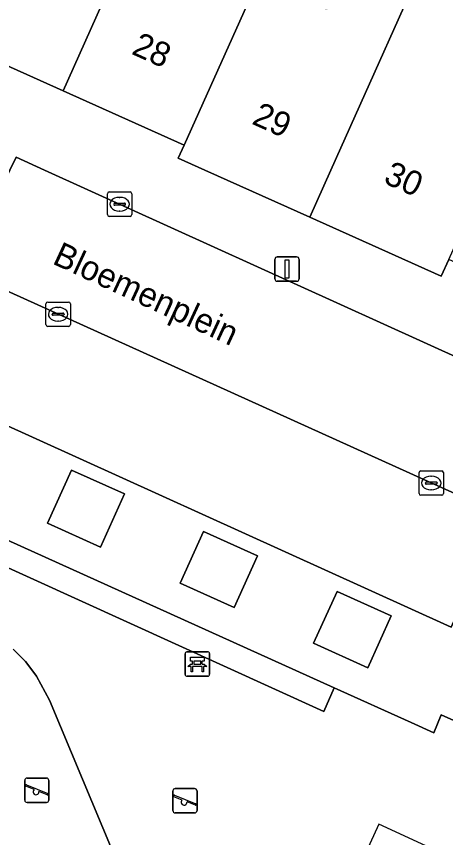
# Model space of a CAD drawing. Extents: x 161838 to 162344, y 381620 to 382160.
# Drawn here: x 162191.19 to 162208.76, y 381722.64 to 381756.3 of the extents above; entities that cross this region are included whole.
import ezdxf

# ---------------------------------------------------------------- set-up
doc = ezdxf.new("R2010")
doc.units = 0
for name, color, linetype in [('IMGEO_Bank', 7, 'Continuous'), ('IMGEO_Groenvoorziening', 7, 'Continuous'), ('IMGEO_Haag', 7, 'Continuous'), ('IMGEO_Hek', 7, 'Continuous'), ('IMGEO_Kolk', 7, 'Continuous'), ('IMGEO_Lichtmast', 7, 'Continuous'), ('IMGEO_Openbare_ruimte_label', 7, 'Continuous'), ('IMGEO_Pand', 7, 'Continuous'), ('IMGEO_Pand_nummerreeks', 7, 'Continuous'), ('IMGEO_Parkeervlak_open', 7, 'Continuous'), ('IMGEO_Rijbaan_lokaal_open', 7, 'Continuous'), ('IMGEO_Speelvoorziening', 7, 'Continuous'), ('IMGEO_Terreindeel_zand', 7, 'Continuous'), ('IMGEO_Voetpad_open', 7, 'Continuous')]:
    doc.layers.add(name, color=color, linetype=linetype)

msp = doc.modelspace()

# ---------------------------------------------------------------- linework, layer by layer
at = {"layer": 'IMGEO_Bank'}
for p, q in [((162198.099, 381729.327), (162198.099, 381730.168)), ((162198.099, 381730.168), (162198.099, 381729.327)), ((162198.174, 381730.252), (162199.015, 381730.252)), ((162199.015, 381730.252), (162198.174, 381730.252)), ((162199.099, 381730.177), (162199.099, 381729.336)), ((162199.099, 381729.336), (162199.099, 381730.177)), ((162198.408, 381729.758), (162198.408, 381729.864)), ((162198.452, 381729.864), (162198.452, 381729.758)), ((162198.74, 381729.87), (162198.458, 381729.87)), ((162198.746, 381729.758), (162198.746, 381729.864)), ((162198.79, 381729.864), (162198.79, 381729.758)), ((162198.796, 381729.65), (162198.403, 381729.65)), ((162198.458, 381729.752), (162198.74, 381729.752)), ((162199.024, 381729.252), (162198.183, 381729.252)), ((162198.183, 381729.252), (162199.024, 381729.252))]:
    msp.add_line(p, q, dxfattribs=at)
for points in [[(162198.402, 381729.87), (162198.316, 381729.87), (162198.316, 381730.031), (162198.879, 381730.031), (162198.879, 381729.87), (162198.796, 381729.87)], [(162198.346, 381729.65), (162198.204, 381729.65), (162198.316, 381729.752), (162198.402, 381729.752)], [(162198.396, 381729.643), (162198.396, 381729.436), (162198.353, 381729.436), (162198.353, 381729.643)], [(162198.796, 381729.752), (162198.879, 381729.752), (162198.991, 381729.65), (162198.852, 381729.65)], [(162198.846, 381729.643), (162198.846, 381729.436), (162198.802, 381729.436), (162198.802, 381729.643)]]:
    msp.add_lwpolyline(points, dxfattribs=at)
for centre, radius, start, end in [((162198.177, 381730.174), 0.0779, 92.4484, 184.2845), ((162198.177, 381730.174), 0.0779, 92.4484, 184.2845), ((162199.021, 381730.174), 0.0779, 2.4484, 94.2845), ((162199.021, 381730.174), 0.0779, 2.4484, 94.2845), ((162198.401, 381729.863), 0.00671, 2.8957, 87.1043), ((162198.458, 381729.863), 0.00671, 92.8957, 177.1043), ((162198.74, 381729.863), 0.00671, 2.8957, 87.1043), ((162198.797, 381729.863), 0.00671, 92.8957, 177.1043), ((162198.346, 381729.643), 0.00671, 2.8957, 87.1043), ((162198.403, 381729.643), 0.00671, 92.8957, 177.1043), ((162198.401, 381729.759), 0.00671, 272.8957, 357.1043), ((162198.458, 381729.759), 0.00671, 182.8957, 267.1043), ((162198.74, 381729.759), 0.00671, 272.8957, 357.1043), ((162198.797, 381729.759), 0.00671, 182.8957, 267.1043), ((162198.795, 381729.643), 0.00671, 2.8957, 87.1043), ((162198.852, 381729.643), 0.00671, 92.8957, 177.1043), ((162198.177, 381729.33), 0.0779, 182.4484, 274.2845), ((162198.177, 381729.33), 0.0779, 182.4484, 274.2845), ((162199.021, 381729.33), 0.0779, 272.4484, 4.2845), ((162199.021, 381729.33), 0.0779, 272.4484, 4.2845)]:
    msp.add_arc(centre, radius, start, end, dxfattribs=at)
at = {"layer": 'IMGEO_Groenvoorziening'}
for points in [[(162224.972, 381729.54), (162213.092, 381734.851), (162212.642, 381733.768), (162211.534, 381734.306), (162210.084, 381730.982), (162212.783, 381729.769), (162211.371, 381726.432), (162208.583, 381727.67), (162208.284, 381726.931), (162207.356, 381727.351), (162204.208, 381728.775), (162203.782, 381727.8), (162185.802, 381735.987), (162186.225, 381736.908), (162183.113, 381738.321), (162181.971, 381738.914), (162180.968, 381740.762), (162179.108, 381743.016)], [(162191.06, 381730.357), (162191.564, 381729.849), (162191.947, 381729.349), (162192.014, 381729.249), (162192.541, 381728.271), (162195.625, 381720.87)]]:
    msp.add_lwpolyline(points, dxfattribs=at)
for points in [[(162194.629, 381734.546), (162195.615, 381736.725), (162193.453, 381737.702), (162192.467, 381735.523)], [(162186.225, 381736.908), (162185.802, 381735.987), (162203.782, 381727.8), (162204.208, 381728.775)], [(162200.11, 381732.065), (162201.069, 381734.186), (162198.858, 381735.186), (162197.899, 381733.065)], [(162205.581, 381729.598), (162206.542, 381731.724), (162204.325, 381732.727), (162203.363, 381730.601)]]:
    msp.add_lwpolyline(points, close=True, dxfattribs=at)
at = {"layer": 'IMGEO_Haag'}
msp.add_lwpolyline([(162186.225, 381736.908), (162185.802, 381735.987), (162203.782, 381727.8), (162204.208, 381728.775)], close=True, dxfattribs=at)
at = {"layer": 'IMGEO_Hek'}
for points in [[(162206.028, 381723.192), (162200.769, 381711.668), (162200.712, 381710.292), (162201.108, 381709.061), (162201.974, 381708.184), (162206.767, 381705.976)], [(162212.925, 381719.997), (162206.028, 381723.192)]]:
    msp.add_lwpolyline(points, dxfattribs=at)
at = {"layer": 'IMGEO_Kolk'}
for p, q in [((162194.917, 381748.179), (162194.917, 381749.031)), ((162194.992, 381749.105), (162195.844, 381749.105)), ((162195.918, 381749.031), (162195.918, 381748.179)), ((162195.405, 381748.885), (162195.43, 381748.885)), ((162195.176, 381748.599), (162195.176, 381748.611)), ((162195.614, 381748.562), (162195.216, 381748.562)), ((162195.219, 381748.648), (162195.617, 381748.648)), ((162195.66, 381748.611), (162195.66, 381748.599)), ((162195.844, 381748.105), (162194.992, 381748.105)), ((162195.428, 381748.325), (162195.403, 381748.325)), ((162192.399, 381743.667), (162192.399, 381744.519)), ((162192.474, 381744.593), (162193.326, 381744.593)), ((162192.887, 381744.373), (162192.912, 381744.373)), ((162193.4, 381744.519), (162193.4, 381743.667)), ((162192.658, 381744.087), (162192.658, 381744.099)), ((162193.096, 381744.05), (162192.698, 381744.05)), ((162192.701, 381744.136), (162193.099, 381744.136)), ((162193.142, 381744.099), (162193.142, 381744.087)), ((162192.91, 381743.813), (162192.885, 381743.813)), ((162193.326, 381743.593), (162192.474, 381743.593)), ((162207.678, 381736.746), (162207.678, 381737.598)), ((162207.753, 381737.672), (162208.605, 381737.672)), ((162208.679, 381737.598), (162208.679, 381736.746)), ((162208.166, 381737.452), (162208.191, 381737.452)), ((162207.937, 381737.166), (162207.937, 381737.178)), ((162208.375, 381737.129), (162207.977, 381737.129)), ((162207.98, 381737.215), (162208.378, 381737.215)), ((162208.189, 381736.892), (162208.164, 381736.892)), ((162208.421, 381737.178), (162208.421, 381737.166)), ((162208.605, 381736.672), (162207.753, 381736.672))]:
    msp.add_line(p, q, dxfattribs=at)
for points in [[(162194.917, 381748.179), (162194.917, 381749.031)], [(162194.992, 381749.105), (162195.844, 381749.105)], [(162195.918, 381749.031), (162195.918, 381748.179)], [(162195.844, 381748.105), (162194.992, 381748.105)], [(162192.399, 381743.667), (162192.399, 381744.519)], [(162192.474, 381744.593), (162193.326, 381744.593)], [(162193.4, 381744.519), (162193.4, 381743.667)], [(162193.326, 381743.593), (162192.474, 381743.593)], [(162207.678, 381736.746), (162207.678, 381737.598)], [(162207.753, 381737.672), (162208.605, 381737.672)], [(162208.679, 381737.598), (162208.679, 381736.746)], [(162208.605, 381736.672), (162207.753, 381736.672)]]:
    msp.add_lwpolyline(points, dxfattribs=at)
for centre, radius, start, end in [((162194.994, 381749.029), 0.0765, 91.552, 178.448), ((162194.994, 381749.029), 0.0765, 91.552, 178.448), ((162195.842, 381749.029), 0.0765, 1.552, 88.448), ((162195.842, 381749.029), 0.0765, 1.552, 88.448), ((162195.216, 381748.608), 0.0403, 85.8775, 175.7526), ((162195.213, 381748.598), 0.0366, 178.938, 274.7102), ((162195.617, 381748.605), 0.043, 264.8664, 352.4533), ((162195.621, 381748.61), 0.0386, 1.7309, 96.639), ((162194.994, 381748.181), 0.0765, 181.552, 268.448), ((162194.994, 381748.181), 0.0765, 181.552, 268.448), ((162195.842, 381748.181), 0.0765, 271.552, 358.448), ((162195.842, 381748.181), 0.0765, 271.552, 358.448), ((162192.476, 381744.517), 0.0765, 91.552, 178.448), ((162192.476, 381744.517), 0.0765, 91.552, 178.448), ((162193.324, 381744.517), 0.0765, 1.552, 88.448), ((162193.324, 381744.517), 0.0765, 1.552, 88.448), ((162192.698, 381744.096), 0.0403, 85.8775, 175.7526), ((162192.695, 381744.086), 0.0366, 178.938, 274.7102), ((162193.099, 381744.093), 0.043, 264.8664, 352.4533), ((162193.103, 381744.098), 0.0386, 1.7309, 96.639), ((162192.476, 381743.669), 0.0765, 181.552, 268.448), ((162192.476, 381743.669), 0.0765, 181.552, 268.448), ((162193.324, 381743.669), 0.0765, 271.552, 358.448), ((162193.324, 381743.669), 0.0765, 271.552, 358.448), ((162207.755, 381737.596), 0.0765, 91.552, 178.448), ((162207.755, 381737.596), 0.0765, 91.552, 178.448), ((162208.603, 381737.596), 0.0765, 1.552, 88.448), ((162208.603, 381737.596), 0.0765, 1.552, 88.448), ((162207.977, 381737.175), 0.0403, 85.8775, 175.7526), ((162207.974, 381737.165), 0.0366, 178.938, 274.7102), ((162208.378, 381737.172), 0.043, 264.8664, 352.4533), ((162208.382, 381737.177), 0.0386, 1.7309, 96.639), ((162207.755, 381736.748), 0.0765, 181.552, 268.448), ((162207.755, 381736.748), 0.0765, 181.552, 268.448), ((162208.603, 381736.748), 0.0765, 271.552, 358.448), ((162208.603, 381736.748), 0.0765, 271.552, 358.448)]:
    msp.add_arc(centre, radius, start, end, dxfattribs=at)
for centre, major_axis, ratio, start_param, end_param in [((162195.404, 381748.605), (-0.387, 0.002), 0.722429, 4.712389, 7.853982), ((162195.429, 381748.605), (-0.39, 0.002), 0.717154, 1.570796, 4.712389), ((162192.886, 381744.093), (-0.387, 0.002), 0.722429, 4.712389, 7.853982), ((162192.911, 381744.093), (-0.39, 0.002), 0.717154, 1.570796, 4.712389), ((162208.165, 381737.172), (-0.387, 0.002), 0.722429, 4.712389, 7.853982), ((162208.19, 381737.172), (-0.39, 0.002), 0.717154, 1.570796, 4.712389)]:
    msp.add_ellipse(centre, major_axis=major_axis, ratio=ratio, start_param=start_param, end_param=end_param, dxfattribs=at)
at = {"layer": 'IMGEO_Lichtmast'}
for p, q in [((162201.775, 381745.543), (162201.775, 381746.343)), ((162201.775, 381746.343), (162201.775, 381745.543)), ((162201.875, 381746.443), (162202.665, 381746.443)), ((162202.665, 381746.443), (162201.875, 381746.443)), ((162202.765, 381746.343), (162202.765, 381745.543)), ((162202.765, 381745.543), (162202.765, 381746.343)), ((162202.665, 381745.443), (162201.875, 381745.443)), ((162201.875, 381745.443), (162202.665, 381745.443))]:
    msp.add_line(p, q, dxfattribs=at)
msp.add_lwpolyline([(162202.195, 381746.318), (162202.345, 381746.318), (162202.345, 381745.568), (162202.195, 381745.568), (162202.195, 381746.318)], dxfattribs=at)
for centre, start, end in [((162201.875, 381746.343), 90, 180), ((162201.875, 381746.343), 90, 180), ((162202.665, 381746.343), 0, 90), ((162202.665, 381746.343), 360, 90), ((162201.875, 381745.543), 180, 270), ((162201.875, 381745.543), 180, 270), ((162202.665, 381745.543), 270, 0), ((162202.665, 381745.543), 270, 0)]:
    msp.add_arc(centre, 0.1, start, end, dxfattribs=at)
at = {"layer": 'IMGEO_Pand'}
for points in [[(162193.104, 381753.256), (162198.281, 381764.843), (162195.529, 381766.079), (162193.363, 381761.254), (162190.855, 381762.38), (162187.836, 381755.622)], [(162201.112, 381757.851), (162198.757, 381758.908), (162200.895, 381763.669), (162198.281, 381764.843), (162193.104, 381753.256), (162198.064, 381751.029)], [(162208.641, 381760.236), (162207.192, 381760.887), (162206.046, 381761.402), (162203.891, 381756.603), (162201.112, 381757.851), (162198.064, 381751.029), (162197.821, 381750.485), (162198.9, 381750), (162203.205, 381748.067), (162204.068, 381750)], [(162208.641, 381760.236), (162204.068, 381750), (162203.205, 381748.067), (162208.591, 381745.649), (162208.902, 381746.34), (162210.536, 381750), (162211.865, 381752.977), (162209.321, 381754.12), (162211.483, 381758.934), (162210.364, 381759.436)]]:
    msp.add_lwpolyline(points, close=True, dxfattribs=at)
at = {"layer": 'IMGEO_Parkeervlak_open'}
msp.add_lwpolyline([(162189.039, 381745.843), (162186.969, 381741.263), (162208.996, 381731.258), (162211.041, 381735.877)], close=True, dxfattribs=at)
at = {"layer": 'IMGEO_Rijbaan_lokaal_open'}
msp.add_lwpolyline([(162189.039, 381745.843), (162211.041, 381735.877), (162211.315, 381736.73), (162212.738, 381736.075), (162213.436, 381737.674), (162214.158, 381739.328), (162212.727, 381739.978), (162213.028, 381740.603), (162192.347, 381750), (162191.178, 381750.531), (162190.923, 381750), (162190.853, 381749.855), (162190.535, 381750), (162189.467, 381750.486), (162189.25, 381750), (162188.765, 381748.912), (162188.044, 381747.294), (162189.465, 381746.646)], close=True, dxfattribs=at)
at = {"layer": 'IMGEO_Speelvoorziening'}
for p, q in [((162191.529, 381724.174), (162191.529, 381724.974)), ((162191.529, 381724.974), (162191.529, 381724.174)), ((162191.598, 381724.799), (162192.474, 381724.446)), ((162191.629, 381725.074), (162192.419, 381725.074)), ((162192.419, 381725.074), (162191.629, 381725.074)), ((162192.519, 381724.974), (162192.519, 381724.174)), ((162192.519, 381724.174), (162192.519, 381724.974)), ((162191.912, 381724.602), (162191.573, 381724.739)), ((162192.45, 381724.386), (162192.11, 381724.523)), ((162197.597, 381723.748), (162197.597, 381724.548)), ((162197.597, 381724.548), (162197.597, 381723.748)), ((162197.697, 381724.648), (162198.487, 381724.648)), ((162198.487, 381724.648), (162197.697, 381724.648)), ((162198.587, 381724.548), (162198.587, 381723.748)), ((162198.587, 381723.748), (162198.587, 381724.548)), ((162197.98, 381724.176), (162197.641, 381724.313)), ((162197.666, 381724.373), (162198.542, 381724.02)), ((162198.518, 381723.96), (162198.178, 381724.097)), ((162192.419, 381724.074), (162191.629, 381724.074)), ((162191.629, 381724.074), (162192.419, 381724.074)), ((162198.487, 381723.648), (162197.697, 381723.648)), ((162197.697, 381723.648), (162198.487, 381723.648))]:
    msp.add_line(p, q, dxfattribs=at)
for centre, radius, start, end in [((162191.629, 381724.974), 0.1, 90, 180), ((162191.629, 381724.974), 0.1, 90, 180), ((162191.586, 381724.769), 0.0327, 68.078, 248.078), ((162192.419, 381724.974), 0.1, 0, 90), ((162192.419, 381724.974), 0.1, 360, 90), ((162191.991, 381724.512), 0.12, 130.9928, 5.1632), ((162192.462, 381724.416), 0.0327, 248.078, 68.078), ((162197.697, 381724.548), 0.1, 90, 180), ((162197.697, 381724.548), 0.1, 90, 180), ((162198.487, 381724.548), 0.1, 0, 90), ((162198.487, 381724.548), 0.1, 360, 90), ((162191.629, 381724.174), 0.1, 180, 270), ((162191.629, 381724.174), 0.1, 180, 270), ((162192.419, 381724.174), 0.1, 270, 0), ((162192.419, 381724.174), 0.1, 270, 0), ((162197.654, 381724.343), 0.0327, 68.078, 248.078), ((162198.059, 381724.086), 0.12, 130.9928, 5.1632), ((162198.53, 381723.99), 0.0327, 248.078, 68.078), ((162197.697, 381723.748), 0.1, 180, 270), ((162197.697, 381723.748), 0.1, 180, 270), ((162198.487, 381723.748), 0.1, 270, 0), ((162198.487, 381723.748), 0.1, 270, 0)]:
    msp.add_arc(centre, radius, start, end, dxfattribs=at)
at = {"layer": 'IMGEO_Terreindeel_zand'}
msp.add_lwpolyline([(162195.625, 381720.87), (162192.541, 381728.271), (162192.014, 381729.249), (162191.947, 381729.349), (162191.564, 381729.849), (162191.06, 381730.357)], dxfattribs=at)
at = {"layer": 'IMGEO_Voetpad_open'}
for points in [[(162232.959, 381732.091), (162232.318, 381735.731), (162229.597, 381736.925), (162224.172, 381739.307), (162218.962, 381741.594), (162219.047, 381741.785), (162213.925, 381744.085), (162208.902, 381746.34), (162208.591, 381745.649), (162203.205, 381748.067), (162198.9, 381750), (162197.821, 381750.485), (162198.064, 381751.029), (162193.104, 381753.256), (162187.836, 381755.622), (162187.753, 381755.439), (162183.881, 381757.177), (162183.972, 381757.38), (162182.722, 381757.941)], [(162177.611, 381755.882), (162187.28, 381751.481), (162189.467, 381750.486), (162190.535, 381750), (162190.853, 381749.855), (162190.923, 381750), (162191.178, 381750.531), (162192.347, 381750), (162213.028, 381740.603), (162212.727, 381739.978), (162214.158, 381739.328), (162216.362, 381738.355), (162228.873, 381732.865)]]:
    msp.add_lwpolyline(points, dxfattribs=at)
for points in [[(162210.084, 381730.982), (162211.534, 381734.306), (162212.642, 381733.768), (162213.092, 381734.851), (162211.041, 381735.877), (162208.996, 381731.258), (162186.969, 381741.263), (162189.039, 381745.843), (162186.964, 381746.704), (162186.502, 381745.647), (162183.113, 381738.321), (162186.225, 381736.908), (162204.208, 381728.775), (162207.356, 381727.351), (162208.284, 381726.931), (162208.583, 381727.67), (162211.371, 381726.432), (162212.783, 381729.769)], [(162194.629, 381734.546), (162192.467, 381735.523), (162193.453, 381737.702), (162195.615, 381736.725)], [(162200.11, 381732.065), (162197.899, 381733.065), (162198.858, 381735.186), (162201.069, 381734.186)], [(162206.542, 381731.724), (162205.581, 381729.598), (162203.363, 381730.601), (162204.325, 381732.727)]]:
    msp.add_lwpolyline(points, close=True, dxfattribs=at)

# ---------------------------------------------------------------- texts
at = {"layer": 'IMGEO_Openbare_ruimte_label'}
msp.add_text('Bloemenplein', height=1, rotation=335.1769, dxfattribs=at).set_placement((162192.621, 381746.182))
at = {"layer": 'IMGEO_Pand_nummerreeks'}
for s, rotation, p in [('28', 335.8212, (162195.864, 381754.779)), ('29', 335.8269, (162200.789, 381751.914)), ('30', 335.8155, (162206.18, 381749.495))]:
    msp.add_text(s, height=1, rotation=rotation, dxfattribs=at).set_placement(p)

doc.saveas('drawing.dxf')
